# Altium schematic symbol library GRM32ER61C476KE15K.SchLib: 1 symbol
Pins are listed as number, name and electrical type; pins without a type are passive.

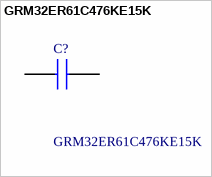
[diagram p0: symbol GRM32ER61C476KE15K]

## GRM32ER61C476KE15K
designator C?
Murata 1210 GRM 47uF Ceramic Multilayer Capacitor, 16 V, +85C, X5R Dielectric, +/-10% SMD; Manufacturer_Name: Murata Electronics; Geometry.Height: 2.7mm
footprint CAPC3225X270N
pins: 1, 2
